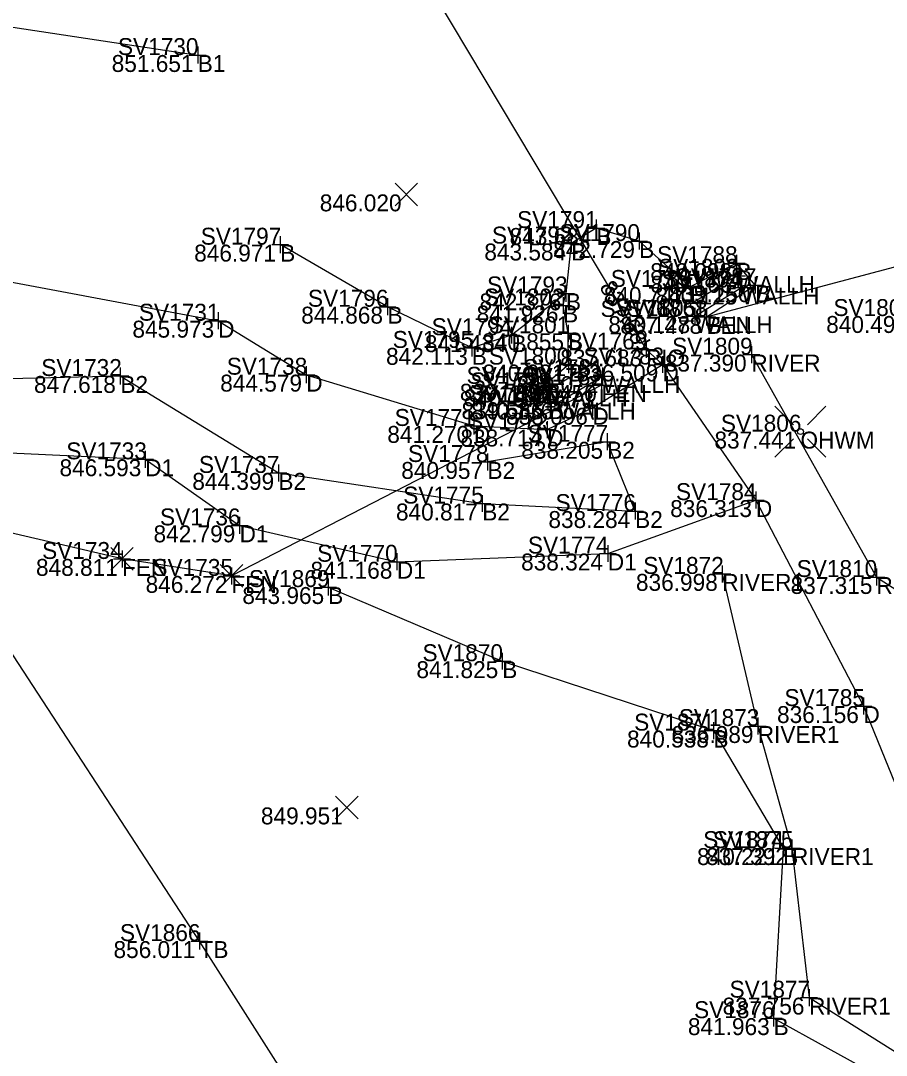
# Model space of a CAD drawing. Extents: x 2125299 to 2129212, y 713100 to 714300.
# Drawn here: x 2127717.6 to 2127768.7, y 713609 to 713670.1 of the extents above; entities that cross this region are included whole.
import ezdxf

# ---------------------------------------------------------------- set-up
doc = ezdxf.new("R2010")
doc.units = 0
for name, color, linetype in [('DR_X_Ditch', 7, 'Continuous'), ('DR_X_Headwall', 7, 'Continuous'), ('DR_X_Storm_Sewer', 7, 'Continuous'), ('HY_X_Water_Edge', 7, 'Continuous'), ('RD_X_Fence', 7, 'Continuous'), ('RW_P_Esmt_TMP', 7, 'Continuous'), ('RW_X_CL_100_Cardinal_Points', 7, 'Continuous'), ('RW_X_Esmt_CH', 7, 'Continuous'), ('RW_X_Fee_WL', 7, 'Continuous'), ('SC_Scratch1', 7, 'Continuous'), ('SV_X_Break_Lines', 7, 'Continuous'), ('SV_X_Mon_Cells_Found', 7, 'Continuous'), ('SV_X_Text_Elevation', 7, 'Continuous'), ('SV_X_Text_Name', 7, 'Continuous'), ('SV_X_Top_of_Bank', 7, 'Continuous')]:
    doc.layers.add(name, color=color, linetype=linetype)

msp = doc.modelspace()

# ---------------------------------------------------------------- linework, layer by layer
at = {"layer": 'DR_X_Ditch'}
for points in [[(2127620.934, 713659.023), (2127638.79, 713663.526), (2127657.337, 713667.277), (2127679.511, 713661.223), (2127699.228, 713657.403), (2127713.383, 713655.358), (2127729.25, 713652.396), (2127734.458, 713649.207), (2127744.361, 713646.178), (2127748.689, 713645.966), (2127751.366, 713647.251), (2127755.508, 713649.81)], [(2127754.532, 713650.693), (2127755.508, 713649.81), (2127761.022, 713641.797), (2127767.377, 713629.627), (2127773.825, 713613.836), (2127787.097, 713602.059), (2127796.409, 713596.425), (2127812.41, 713592.759), (2127822.136, 713591.387), (2127830.865, 713593.325), (2127835.513, 713593.154), (2127840.963, 713588.862), (2127844.441, 713576.862)], [(2127700.68, 713644.289), (2127707.664, 713645.028), (2127724.942, 713644.207), (2127730.518, 713640.303), (2127739.813, 713638.154), (2127752.274, 713638.64), (2127761.022, 713641.797)]]:
    msp.add_lwpolyline(points, dxfattribs=at)
at = {"layer": 'DR_X_Headwall'}
for p, q in [((2127759.907, 713655.047), (2127757.149, 713653.356)), ((2127757.149, 713653.356), (2127757.408, 713652.663)), ((2127757.408, 713652.663), (2127757.408, 713652.663)), ((2127751.484, 713649.906), (2127748.845, 713648.341)), ((2127751.954, 713649.123), (2127751.484, 713649.906))]:
    msp.add_line(p, q, dxfattribs=at)
for points in [[(2127757.408, 713652.663), (2127760.166, 713654.354), (2127759.907, 713655.047)], [(2127748.845, 713648.341), (2127749.315, 713647.558), (2127751.954, 713649.123)]]:
    msp.add_lwpolyline(points, dxfattribs=at)
at = {"layer": 'DR_X_Storm_Sewer'}
msp.add_line((2127551.463, 713991.149), (2127754.532, 713650.693), dxfattribs=at)
at = {"layer": 'HY_X_Water_Edge'}
for points in [[(2127760.756, 713650.39), (2127768.145, 713637.253), (2127774.726, 713633.042), (2127778.539, 713623.49), (2127790.379, 713611.577), (2127799.446, 713605.767), (2127811.759, 713595.2), (2127821.632, 713592.889), (2127831.559, 713597.952), (2127834.894, 713597.211), (2127837.24, 713606.78), (2127846.533, 713615.952), (2127858.456, 713615.157), (2127864.185, 713615.01), (2127868.763, 713619.475), (2127877.26, 713624.249)], [(2127759.038, 713637.436), (2127761.132, 713628.448), (2127763.153, 713621.237), (2127764.162, 713612.401), (2127775.864, 713605.035), (2127792.881, 713593.368), (2127809.847, 713589.645), (2127822.201, 713590.682), (2127831.261, 713591.73)]]:
    msp.add_lwpolyline(points, dxfattribs=at)
at = {"layer": 'RD_X_Fence'}
for points in [[(2127758.111, 713652.62), (2127783.853, 713659.466), (2127880.444, 713686.281), (2127925.778, 713698.517)], [(2127751.903, 713648.595), (2127730.04, 713637.318), (2127723.572, 713638.32), (2127709.175, 713641.673), (2127690.775, 713645.288), (2127644.692, 713654.222), (2127597.812, 713640.572)]]:
    msp.add_lwpolyline(points, dxfattribs=at)
at = {"layer": 'RW_X_CL_100_Cardinal_Points'}
for p, q in [((2127754.532, 713651.193), (2127754.532, 713650.193)), ((2127754.032, 713650.693), (2127755.032, 713650.693)), ((2127754.532, 713650.693), (2127754.532, 713650.693))]:
    msp.add_line(p, q, dxfattribs=at)
at = {"layer": 'SV_X_Break_Lines'}
for points in [[(2127701.234, 713672.152), (2127728.044, 713668.093)], [(2127758.111, 713652.62), (2127760.985, 713654.496), (2127759.884, 713655.797), (2127757.132, 713654.391), (2127754.129, 713657.102), (2127751.595, 713657.871), (2127750.101, 713656.956), (2127749.801, 713654.009), (2127746.586, 713651.541), (2127744.235, 713650.789), (2127739.258, 713653.223), (2127732.917, 713656.889)], [(2127748.733, 713647.582), (2127748.615, 713648.668), (2127749.955, 713649.804), (2127749.923, 713651.651), (2127749.631, 713653.296), (2127749.801, 713654.009)], [(2127690.775, 713645.288), (2127696.03, 713649.562), (2127706.646, 713648.374), (2127713.592, 713648.905), (2127723.473, 713649.13), (2127732.81, 713643.403), (2127744.855, 713641.594), (2127753.887, 713641.149), (2127752.233, 713645.243), (2127745.167, 713644.049)], [(2127735.752, 713636.66), (2127746.037, 713632.28), (2127758.511, 713628.179), (2127762.631, 713621.236), (2127762.072, 713611.189), (2127774.904, 713604.099), (2127791.545, 713591.996), (2127809.166, 713587.988), (2127822.854, 713589.107), (2127830.592, 713589.805), (2127834.63, 713588.796)]]:
    msp.add_lwpolyline(points, dxfattribs=at)
at = {"layer": 'SV_X_Mon_Cells_Found'}
for p, q in [((2127727.544, 713668.093), (2127728.544, 713668.093)), ((2127728.044, 713668.593), (2127728.044, 713667.593)), ((2127728.044, 713668.093), (2127728.044, 713668.093)), ((2127751.595, 713658.371), (2127751.595, 713657.371)), ((2127751.095, 713657.871), (2127752.095, 713657.871)), ((2127751.595, 713657.871), (2127751.595, 713657.871)), ((2127732.917, 713657.389), (2127732.917, 713656.389)), ((2127750.101, 713657.456), (2127750.101, 713656.456)), ((2127753.629, 713657.102), (2127754.629, 713657.102)), ((2127754.129, 713657.602), (2127754.129, 713656.602)), ((2127754.129, 713657.102), (2127754.129, 713657.102)), ((2127732.417, 713656.889), (2127733.417, 713656.889)), ((2127732.917, 713656.889), (2127732.917, 713656.889)), ((2127749.601, 713656.956), (2127750.601, 713656.956)), ((2127750.101, 713656.956), (2127750.101, 713656.956)), ((2127759.884, 713656.297), (2127759.884, 713655.297)), ((2127759.384, 713655.797), (2127760.384, 713655.797)), ((2127759.884, 713655.797), (2127759.884, 713655.797)), ((2127759.907, 713655.547), (2127759.907, 713654.547)), ((2127757.132, 713654.891), (2127757.132, 713653.891)), ((2127759.407, 713655.047), (2127760.407, 713655.047)), ((2127759.907, 713655.047), (2127759.907, 713655.047)), ((2127760.166, 713654.854), (2127760.166, 713653.854)), ((2127760.985, 713654.996), (2127760.985, 713653.996)), ((2127749.801, 713654.509), (2127749.801, 713653.509)), ((2127756.632, 713654.391), (2127757.632, 713654.391)), ((2127757.132, 713654.391), (2127757.132, 713654.391)), ((2127759.666, 713654.354), (2127760.666, 713654.354)), ((2127760.166, 713654.354), (2127760.166, 713654.354)), ((2127760.485, 713654.496), (2127761.485, 713654.496)), ((2127760.985, 713654.496), (2127760.985, 713654.496)), ((2127739.258, 713653.723), (2127739.258, 713652.723)), ((2127749.301, 713654.009), (2127750.301, 713654.009)), ((2127749.631, 713653.796), (2127749.631, 713652.796)), ((2127749.801, 713654.009), (2127749.801, 713654.009)), ((2127729.25, 713652.896), (2127729.25, 713651.896)), ((2127738.758, 713653.223), (2127739.758, 713653.223)), ((2127739.258, 713653.223), (2127739.258, 713653.223)), ((2127749.131, 713653.296), (2127750.131, 713653.296)), ((2127749.631, 713653.296), (2127749.631, 713653.296)), ((2127757.408, 713653.163), (2127757.408, 713652.163)), ((2127758.111, 713653.12), (2127758.111, 713652.12)), ((2127758.111, 713653.12), (2127758.111, 713652.12)), ((2127728.75, 713652.396), (2127729.75, 713652.396)), ((2127729.25, 713652.396), (2127729.25, 713652.396)), ((2127756.908, 713652.663), (2127757.908, 713652.663)), ((2127757.408, 713652.663), (2127757.408, 713652.663)), ((2127757.611, 713652.62), (2127758.611, 713652.62)), ((2127757.611, 713652.62), (2127758.611, 713652.62)), ((2127758.111, 713652.62), (2127758.111, 713652.62)), ((2127758.111, 713652.62), (2127758.111, 713652.62)), ((2127746.586, 713652.041), (2127746.586, 713651.041)), ((2127749.423, 713651.651), (2127750.423, 713651.651)), ((2127749.923, 713652.151), (2127749.923, 713651.151)), ((2127749.923, 713651.651), (2127749.923, 713651.651)), ((2127744.235, 713651.289), (2127744.235, 713650.289)), ((2127746.086, 713651.541), (2127747.086, 713651.541)), ((2127746.586, 713651.541), (2127746.586, 713651.541)), ((2127743.735, 713650.789), (2127744.735, 713650.789)), ((2127744.235, 713650.789), (2127744.235, 713650.789)), ((2127760.256, 713650.39), (2127761.256, 713650.39)), ((2127760.756, 713650.89), (2127760.756, 713649.89)), ((2127760.756, 713650.39), (2127760.756, 713650.39)), ((2127749.455, 713649.804), (2127750.455, 713649.804)), ((2127749.955, 713650.304), (2127749.955, 713649.304)), ((2127749.955, 713649.804), (2127749.955, 713649.804)), ((2127755.008, 713649.81), (2127756.008, 713649.81)), ((2127755.508, 713650.31), (2127755.508, 713649.31)), ((2127755.508, 713649.81), (2127755.508, 713649.81)), ((2127722.973, 713649.13), (2127723.973, 713649.13)), ((2127723.473, 713649.63), (2127723.473, 713648.63)), ((2127723.473, 713649.13), (2127723.473, 713649.13)), ((2127733.958, 713649.207), (2127734.958, 713649.207)), ((2127734.458, 713649.707), (2127734.458, 713648.707)), ((2127734.458, 713649.207), (2127734.458, 713649.207)), ((2127748.615, 713649.168), (2127748.615, 713648.168)), ((2127751.454, 713649.123), (2127752.454, 713649.123)), ((2127751.954, 713649.623), (2127751.954, 713648.623)), ((2127751.954, 713649.123), (2127751.954, 713649.123)), ((2127748.115, 713648.668), (2127749.115, 713648.668)), ((2127748.615, 713648.668), (2127748.615, 713648.668)), ((2127748.845, 713648.841), (2127748.845, 713647.841)), ((2127751.403, 713648.595), (2127752.403, 713648.595)), ((2127751.903, 713649.095), (2127751.903, 713648.095)), ((2127751.903, 713648.595), (2127751.903, 713648.595)), ((2127748.345, 713648.341), (2127749.345, 713648.341)), ((2127748.733, 713648.082), (2127748.733, 713647.082)), ((2127748.845, 713648.341), (2127748.845, 713648.341)), ((2127749.315, 713648.058), (2127749.315, 713647.058)), ((2127748.233, 713647.582), (2127749.233, 713647.582)), ((2127748.733, 713647.582), (2127748.733, 713647.582)), ((2127748.815, 713647.558), (2127749.815, 713647.558)), ((2127749.315, 713647.558), (2127749.315, 713647.558)), ((2127751.366, 713647.751), (2127751.366, 713646.751)), ((2127744.361, 713646.678), (2127744.361, 713645.678)), ((2127750.866, 713647.251), (2127751.866, 713647.251)), ((2127751.366, 713647.251), (2127751.366, 713647.251)), ((2127743.861, 713646.178), (2127744.861, 713646.178)), ((2127744.361, 713646.178), (2127744.361, 713646.178)), ((2127748.689, 713646.466), (2127748.689, 713645.466)), ((2127748.189, 713645.966), (2127749.189, 713645.966)), ((2127748.689, 713645.966), (2127748.689, 713645.966)), ((2127752.233, 713645.743), (2127752.233, 713644.743)), ((2127751.733, 713645.243), (2127752.733, 713645.243)), ((2127752.233, 713645.243), (2127752.233, 713645.243)), ((2127724.942, 713644.707), (2127724.942, 713643.707)), ((2127745.167, 713644.549), (2127745.167, 713643.549)), ((2127724.442, 713644.207), (2127725.442, 713644.207)), ((2127724.942, 713644.207), (2127724.942, 713644.207)), ((2127732.81, 713643.903), (2127732.81, 713642.903)), ((2127744.667, 713644.049), (2127745.667, 713644.049)), ((2127745.167, 713644.049), (2127745.167, 713644.049)), ((2127732.31, 713643.403), (2127733.31, 713643.403)), ((2127732.81, 713643.403), (2127732.81, 713643.403)), ((2127744.855, 713642.094), (2127744.855, 713641.094)), ((2127760.522, 713641.797), (2127761.522, 713641.797)), ((2127761.022, 713642.297), (2127761.022, 713641.297)), ((2127761.022, 713641.797), (2127761.022, 713641.797)), ((2127744.355, 713641.594), (2127745.355, 713641.594)), ((2127744.855, 713641.594), (2127744.855, 713641.594)), ((2127753.887, 713641.649), (2127753.887, 713640.649)), ((2127730.518, 713640.803), (2127730.518, 713639.803)), ((2127753.387, 713641.149), (2127754.387, 713641.149)), ((2127753.887, 713641.149), (2127753.887, 713641.149)), ((2127730.018, 713640.303), (2127731.018, 713640.303)), ((2127730.518, 713640.303), (2127730.518, 713640.303)), ((2127723.572, 713638.82), (2127723.572, 713637.82)), ((2127752.274, 713639.14), (2127752.274, 713638.14)), ((2127723.072, 713638.32), (2127724.072, 713638.32)), ((2127723.572, 713638.32), (2127723.572, 713638.32)), ((2127739.313, 713638.154), (2127740.313, 713638.154)), ((2127739.813, 713638.654), (2127739.813, 713637.654)), ((2127739.813, 713638.154), (2127739.813, 713638.154)), ((2127751.774, 713638.64), (2127752.774, 713638.64)), ((2127752.274, 713638.64), (2127752.274, 713638.64)), ((2127730.04, 713637.818), (2127730.04, 713636.818)), ((2127759.038, 713637.936), (2127759.038, 713636.936)), ((2127768.145, 713637.753), (2127768.145, 713636.753)), ((2127729.54, 713637.318), (2127730.54, 713637.318)), ((2127730.04, 713637.318), (2127730.04, 713637.318)), ((2127735.752, 713637.16), (2127735.752, 713636.16)), ((2127758.538, 713637.436), (2127759.538, 713637.436)), ((2127759.038, 713637.436), (2127759.038, 713637.436)), ((2127767.645, 713637.253), (2127768.645, 713637.253)), ((2127768.145, 713637.253), (2127768.145, 713637.253)), ((2127735.252, 713636.66), (2127736.252, 713636.66)), ((2127735.752, 713636.66), (2127735.752, 713636.66)), ((2127746.037, 713632.78), (2127746.037, 713631.78)), ((2127745.537, 713632.28), (2127746.537, 713632.28)), ((2127746.037, 713632.28), (2127746.037, 713632.28)), ((2127766.877, 713629.627), (2127767.877, 713629.627)), ((2127767.377, 713630.127), (2127767.377, 713629.127)), ((2127767.377, 713629.627), (2127767.377, 713629.627)), ((2127758.511, 713628.679), (2127758.511, 713627.679)), ((2127760.632, 713628.448), (2127761.632, 713628.448)), ((2127761.132, 713628.948), (2127761.132, 713627.948)), ((2127761.132, 713628.448), (2127761.132, 713628.448)), ((2127758.011, 713628.179), (2127759.011, 713628.179)), ((2127758.511, 713628.179), (2127758.511, 713628.179)), ((2127762.631, 713621.736), (2127762.631, 713620.736)), ((2127763.153, 713621.737), (2127763.153, 713620.737)), ((2127762.131, 713621.236), (2127763.131, 713621.236)), ((2127762.631, 713621.236), (2127762.631, 713621.236)), ((2127762.653, 713621.237), (2127763.653, 713621.237)), ((2127763.153, 713621.237), (2127763.153, 713621.237)), ((2127728.152, 713616.242), (2127728.152, 713615.242)), ((2127727.652, 713615.742), (2127728.652, 713615.742)), ((2127728.152, 713615.742), (2127728.152, 713615.742)), ((2127764.162, 713612.901), (2127764.162, 713611.901)), ((2127763.662, 713612.401), (2127764.662, 713612.401)), ((2127764.162, 713612.401), (2127764.162, 713612.401)), ((2127762.072, 713611.689), (2127762.072, 713610.689)), ((2127761.572, 713611.189), (2127762.572, 713611.189)), ((2127762.072, 713611.189), (2127762.072, 713611.189))]:
    msp.add_line(p, q, dxfattribs=at)
at = {"layer": 'SV_X_Text_Elevation'}
for p, q in [((2127739.702, 713659.19), (2127741.036, 713660.525)), ((2127739.702, 713660.525), (2127741.036, 713659.19)), ((2127722.905, 713637.653), (2127724.239, 713638.988)), ((2127722.905, 713638.988), (2127724.239, 713637.653)), ((2127729.373, 713636.65), (2127730.707, 713637.985)), ((2127729.373, 713637.985), (2127730.707, 713636.65)), ((2127736.195, 713622.972), (2127737.529, 713624.307)), ((2127736.195, 713624.307), (2127737.529, 713622.972))]:
    msp.add_line(p, q, dxfattribs=at)
at = {"layer": 'SV_X_Text_Name'}
for p, q in [((2127762.147, 713647.345), (2127763.24, 713646.252)), ((2127764.074, 713646.252), (2127765.165, 713647.345)), ((2127762.147, 713644.327), (2127763.24, 713645.42)), ((2127764.074, 713645.42), (2127765.165, 713644.327))]:
    msp.add_line(p, q, dxfattribs=at)
msp.add_circle((2127763.657, 713645.842), 0.17, dxfattribs=at)
at = {"layer": 'SV_X_Top_of_Bank'}
msp.add_lwpolyline([(2127791.255, 713553.043), (2127764.66, 713569.483), (2127738.638, 713599.234), (2127728.152, 713615.742), (2127715.103, 713635.711)], dxfattribs=at)

# ---------------------------------------------------------------- texts
at = {"layer": 'RW_P_Esmt_TMP'}
for s, p in [('B1', (2127728.044, 713667.093)), ('B', (2127751.595, 713656.871)), ('B', (2127754.129, 713656.102)), ('B', (2127732.917, 713655.889)), ('B', (2127750.101, 713655.956)), ('B', (2127759.884, 713654.797)), ('WALLH', (2127759.907, 713654.047)), ('B', (2127757.132, 713653.391)), ('WALLH', (2127760.166, 713653.354)), ('B', (2127760.985, 713653.496)), ('B', (2127749.801, 713653.009)), ('B', (2127739.258, 713652.223)), ('B', (2127749.631, 713652.296)), ('D', (2127729.25, 713651.396)), ('WALLH', (2127757.408, 713651.663)), ('B', (2127758.111, 713651.62)), ('FEN', (2127758.111, 713651.62)), ('B', (2127749.923, 713650.651)), ('B', (2127746.586, 713650.542)), ('B', (2127744.235, 713649.789)), ('PIO', (2127754.532, 713649.693)), ('RIVER', (2127760.756, 713649.39)), ('B', (2127749.955, 713648.804)), ('D', (2127755.508, 713648.81)), ('B2', (2127723.473, 713648.13)), ('D', (2127734.458, 713648.207)), ('WALLH', (2127751.954, 713648.123)), ('B', (2127748.615, 713647.668)), ('FEN', (2127751.903, 713647.595)), ('WALLH', (2127748.845, 713647.341)), ('B', (2127748.733, 713646.582)), ('WALLH', (2127749.315, 713646.558)), ('D', (2127751.366, 713646.251)), ('D', (2127744.361, 713645.178)), ('D', (2127748.689, 713644.966)), ('OHWM', (2127763.657, 713644.842)), ('B2', (2127752.233, 713644.243)), ('D1', (2127724.942, 713643.207)), ('B2', (2127745.167, 713643.049)), ('B2', (2127732.81, 713642.403)), ('D', (2127761.022, 713640.797)), ('B2', (2127744.855, 713640.594)), ('B2', (2127753.887, 713640.149)), ('D1', (2127730.518, 713639.303)), ('FEN', (2127723.572, 713637.32)), ('D1', (2127739.813, 713637.154)), ('D1', (2127752.274, 713637.64)), ('FEN', (2127730.04, 713636.318)), ('RIVER1', (2127759.038, 713636.436)), ('RIVER', (2127768.145, 713636.253)), ('B', (2127735.752, 713635.66)), ('B', (2127746.037, 713631.28)), ('D', (2127767.377, 713628.627)), ('RIVER1', (2127761.132, 713627.448)), ('B', (2127758.511, 713627.179)), ('B', (2127762.631, 713620.236)), ('RIVER1', (2127763.153, 713620.237)), ('TB', (2127728.152, 713614.742)), ('RIVER1', (2127764.162, 713611.401)), ('B', (2127762.072, 713610.189))]:
    msp.add_text(s, height=1, dxfattribs=at).set_placement(p)
at = {"layer": 'RW_X_Esmt_CH'}
for s, p in [('SV1730', (2127723.332, 713668.093)), ('SV1791', (2127746.915, 713657.871)), ('SV1797', (2127728.223, 713656.889)), ('SV1792', (2127745.43, 713656.956)), ('SV1790', (2127749.417, 713657.102)), ('SV1788', (2127755.185, 713655.797)), ('SV1803', (2127755.245, 713655.047)), ('SV1789', (2127752.45, 713654.391)), ('SV1804', (2127755.446, 713654.354)), ('SV1787', (2127756.291, 713654.496)), ('SV1793', (2127745.139, 713654.009)), ('SV1796', (2127734.556, 713653.223)), ('SV1802', (2127744.96, 713653.296)), ('SV1731', (2127724.57, 713652.396)), ('SV1768_1', (2127751.848, 713652.62)), ('SV1805', (2127752.739, 713652.663)), ('SV1768', (2127753.412, 713652.62)), ('SV1807', (2127765.605, 713652.673)), ('SV1794', (2127741.866, 713651.541)), ('SV1801', (2127745.243, 713651.651)), ('SV1795', (2127739.566, 713650.789)), ('SV1769', (2127749.85, 713650.693)), ('SV1809', (2127756.074, 713650.39)), ('SV1800', (2127745.243, 713649.804)), ('SV1783', (2127750.846, 713649.81)), ('SV1732', (2127718.802, 713649.13)), ('SV1738', (2127729.759, 713649.207)), ('SV1781', (2127747.274, 713649.123)), ('SV1799', (2127743.933, 713648.668)), ('SV1779', (2127744.163, 713648.341)), ('SV1782', (2127747.232, 713648.595)), ('SV1798', (2127744.034, 713647.582)), ('SV1780', (2127744.603, 713647.558)), ('SV1773', (2127746.704, 713647.251)), ('SV1771', (2127739.681, 713646.178)), ('SV1772', (2127744.018, 713645.966)), ('SV1806', (2127758.955, 713645.842)), ('SV1777', (2127747.539, 713645.243)), ('SV1733', (2127720.28, 713644.207)), ('SV1778', (2127740.468, 713644.049)), ('SV1737', (2127728.116, 713643.403)), ('SV1775', (2127740.186, 713641.594)), ('SV1784', (2127756.302, 713641.797)), ('SV1776', (2127749.185, 713641.149)), ('SV1736', (2127725.816, 713640.303)), ('SV1774', (2127747.554, 713638.64)), ('SV1734', (2127718.852, 713638.32)), ('SV1770', (2127735.101, 713638.154)), ('SV1735', (2127725.371, 713637.318)), ('SV1872', (2127754.367, 713637.436)), ('SV1810', (2127763.433, 713637.253)), ('SV1869', (2127731.07, 713636.66)), ('SV1870', (2127741.325, 713632.28)), ('SV1785', (2127762.708, 713629.627)), ('SV1871', (2127753.831, 713628.179)), ('SV1873', (2127756.47, 713628.448)), ('SV1874', (2127757.911, 713621.236)), ('SV1875', (2127758.484, 713621.237)), ('SV1866', (2127723.45, 713615.742)), ('SV1877', (2127759.468, 713612.401)), ('SV1876', (2127757.37, 713611.189))]:
    msp.add_text(s, height=1, dxfattribs=at).set_placement(p)
at = {"layer": 'RW_X_Fee_WL'}
for s, p in [('851.651', (2127722.962, 713667.093)), ('846.020', (2127735.255, 713658.858)), ('843.684', (2127746.473, 713656.871)), ('842.729', (2127749.045, 713656.102)), ('846.971', (2127727.835, 713655.889)), ('843.584', (2127744.979, 713655.956)), ('840.098', (2127754.784, 713654.797)), ('840.166', (2127754.803, 713654.047)), ('842.376', (2127744.697, 713653.009)), ('840.747', (2127752.036, 713653.391)), ('840.125', (2127755.096, 713653.354)), ('839.150', (2127755.871, 713653.496)), ('844.868', (2127734.158, 713652.223)), ('841.926', (2127744.527, 713652.296)), ('845.973', (2127724.186, 713651.396)), ('840.128', (2127752.308, 713651.663)), ('837.478', (2127753.011, 713651.62)), ('837.478', (2127753.011, 713651.62)), ('840.494', (2127765.177, 713651.673)), ('840.855', (2127744.853, 713650.651)), ('841.434', (2127741.464, 713650.542)), ('842.113', (2127739.171, 713649.789)), ('837.683', (2127749.468, 713649.693)), ('837.390', (2127755.642, 713649.39)), ('840.081', (2127744.873, 713648.804)), ('836.509', (2127750.424, 713648.81)), ('847.618', (2127718.373, 713648.13)), ('844.579', (2127729.374, 713648.207)), ('840.072', (2127746.881, 713648.123)), ('839.719', (2127743.531, 713647.668)), ('837.450', (2127746.789, 713647.595)), ('840.169', (2127743.761, 713647.341)), ('839.586', (2127743.629, 713646.582)), ('840.136', (2127744.211, 713646.558)), ('838.096', (2127746.262, 713646.251)), ('841.270', (2127739.247, 713645.178)), ('838.714', (2127743.567, 713644.966)), ('837.441', (2127758.575, 713644.842)), ('838.205', (2127747.163, 713644.243)), ('846.593', (2127719.878, 713643.207)), ('840.957', (2127740.071, 713643.049)), ('844.399', (2127727.726, 713642.403)), ('836.313', (2127755.958, 713640.797)), ('840.817', (2127739.759, 713640.594)), ('838.284', (2127748.765, 713640.149)), ('842.799', (2127725.434, 713639.303)), ('848.811', (2127718.49, 713637.32)), ('848.811', (2127718.49, 713637.32)), ('841.168', (2127734.713, 713637.154)), ('838.324', (2127747.152, 713637.64)), ('846.272', (2127724.967, 713636.318)), ('846.272', (2127724.967, 713636.318)), ('836.998', (2127753.938, 713636.436)), ('837.315', (2127763.075, 713636.253)), ('843.965', (2127730.682, 713635.66)), ('841.825', (2127740.967, 713631.28)), ('836.156', (2127762.273, 713628.627)), ('836.989', (2127756.048, 713627.448)), ('840.538', (2127753.411, 713627.179)), ('849.951', (2127731.78, 713622.639)), ('840.221', (2127757.549, 713620.236)), ('837.392', (2127758.08, 713620.237)), ('856.011', (2127723.07, 713614.742)), ('837.756', (2127759.058, 713611.401)), ('841.963', (2127757.008, 713610.189))]:
    msp.add_text(s, height=1, dxfattribs=at).set_placement(p)
at = {"layer": 'SC_Scratch1'}
msp.add_text("837.68'", height=1, rotation=300.81448, dxfattribs=at).set_placement((2127751.747, 713654.386))

doc.saveas('drawing.dxf')
